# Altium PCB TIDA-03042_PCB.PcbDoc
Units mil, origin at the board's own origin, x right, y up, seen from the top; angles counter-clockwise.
Board outline 1000 x 1000 mil, 4 copper layers (Top Layer, GND, POWER_SPLIT_PLANE, Bottom Layer), stack 0 mil thick; 34 components, 18 nets, 98 pads, 123 vias.
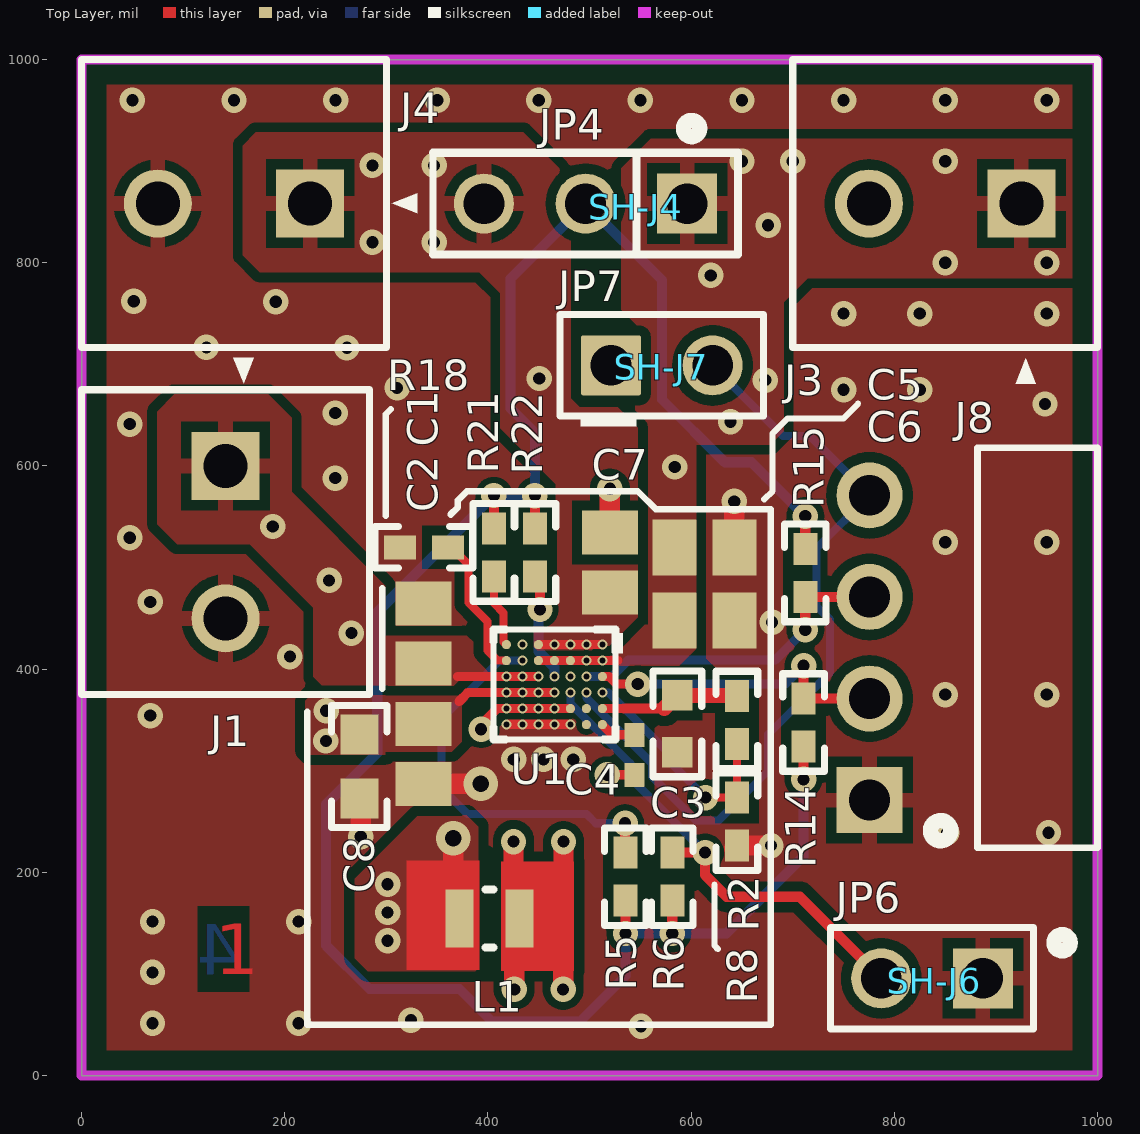
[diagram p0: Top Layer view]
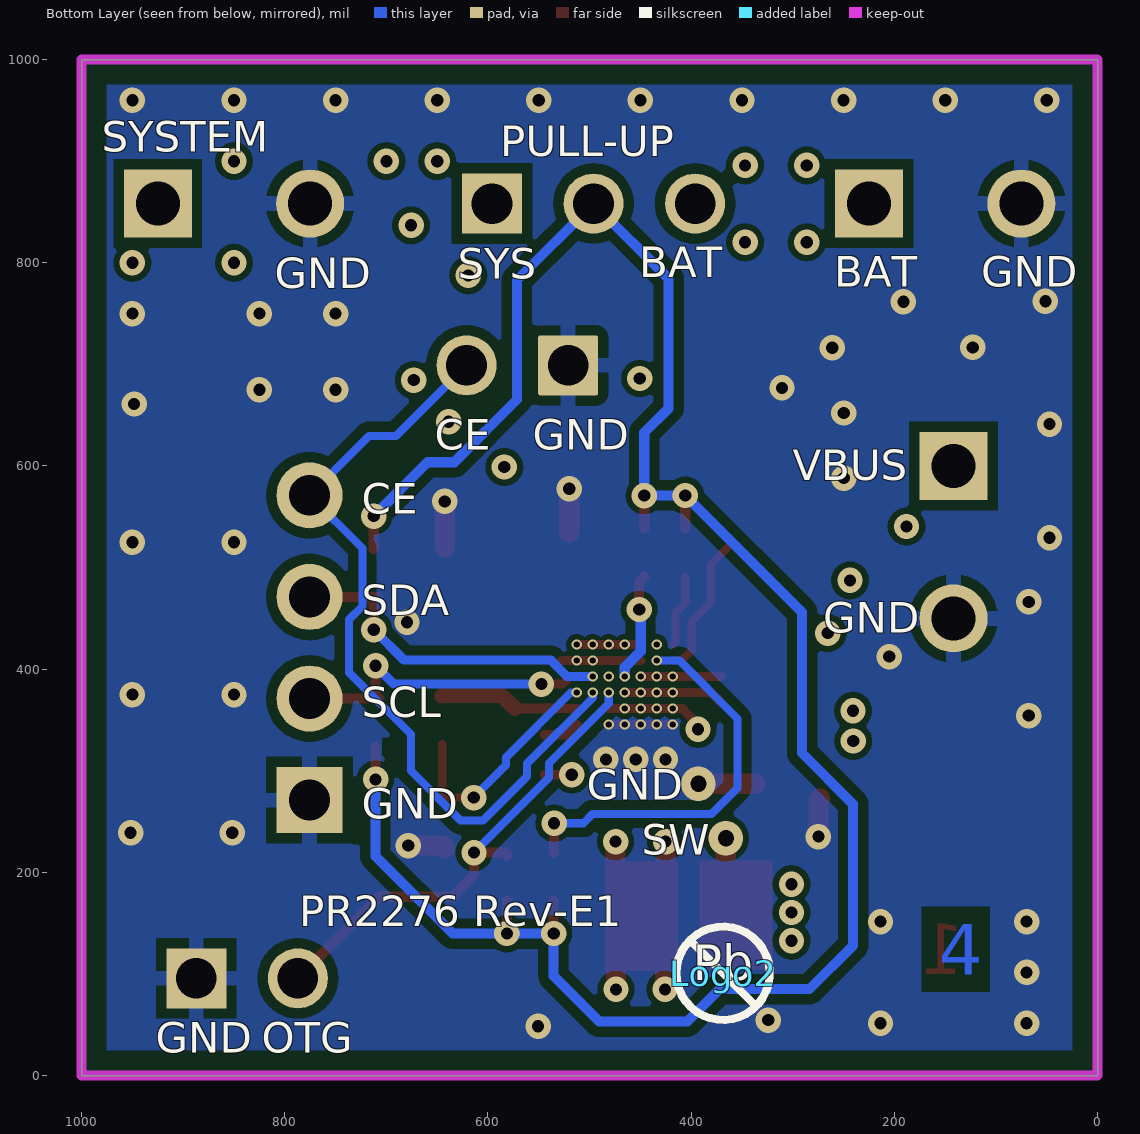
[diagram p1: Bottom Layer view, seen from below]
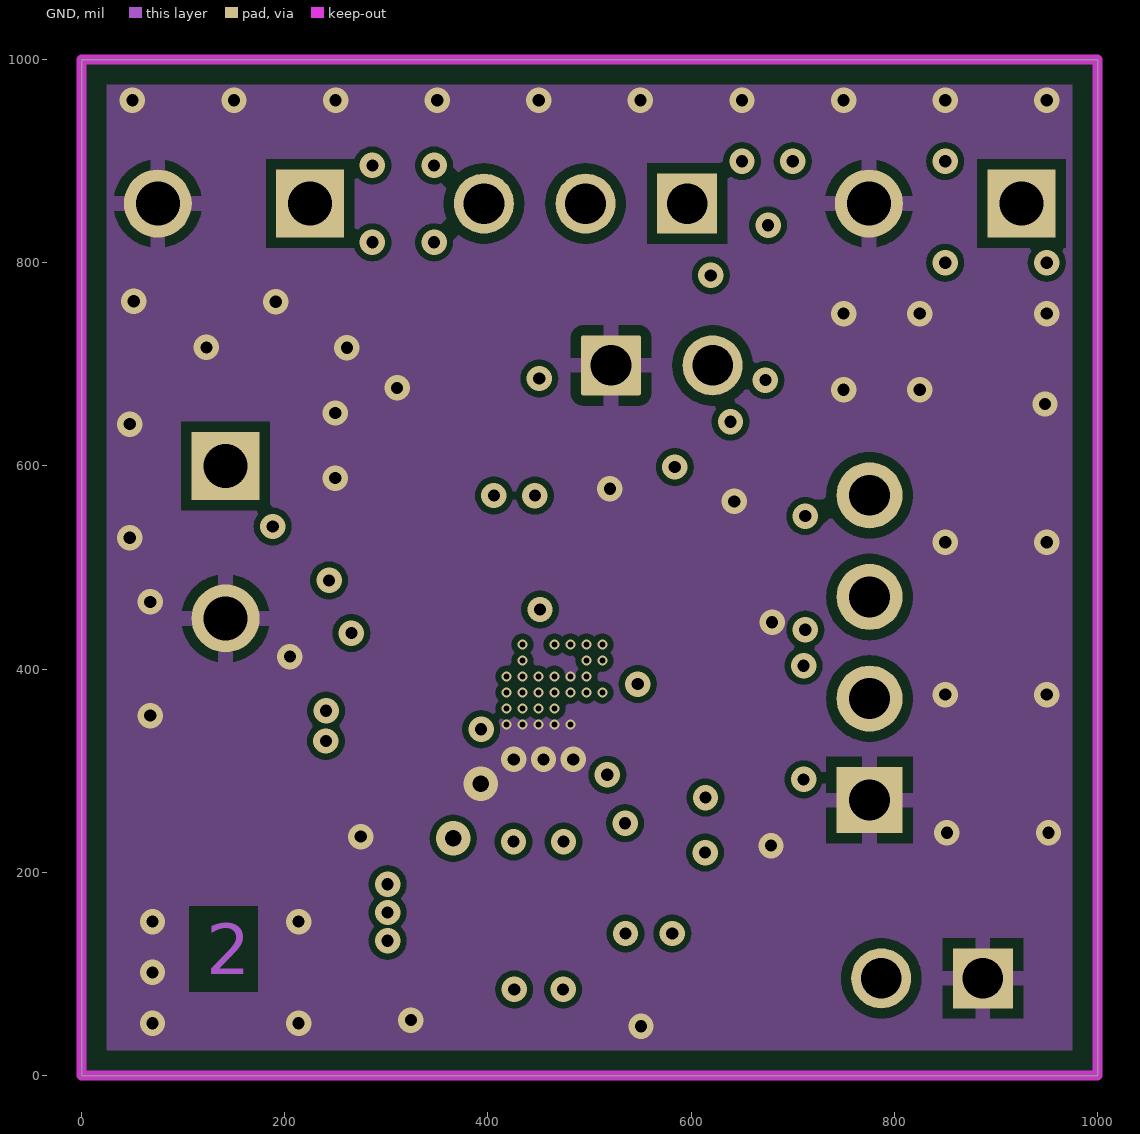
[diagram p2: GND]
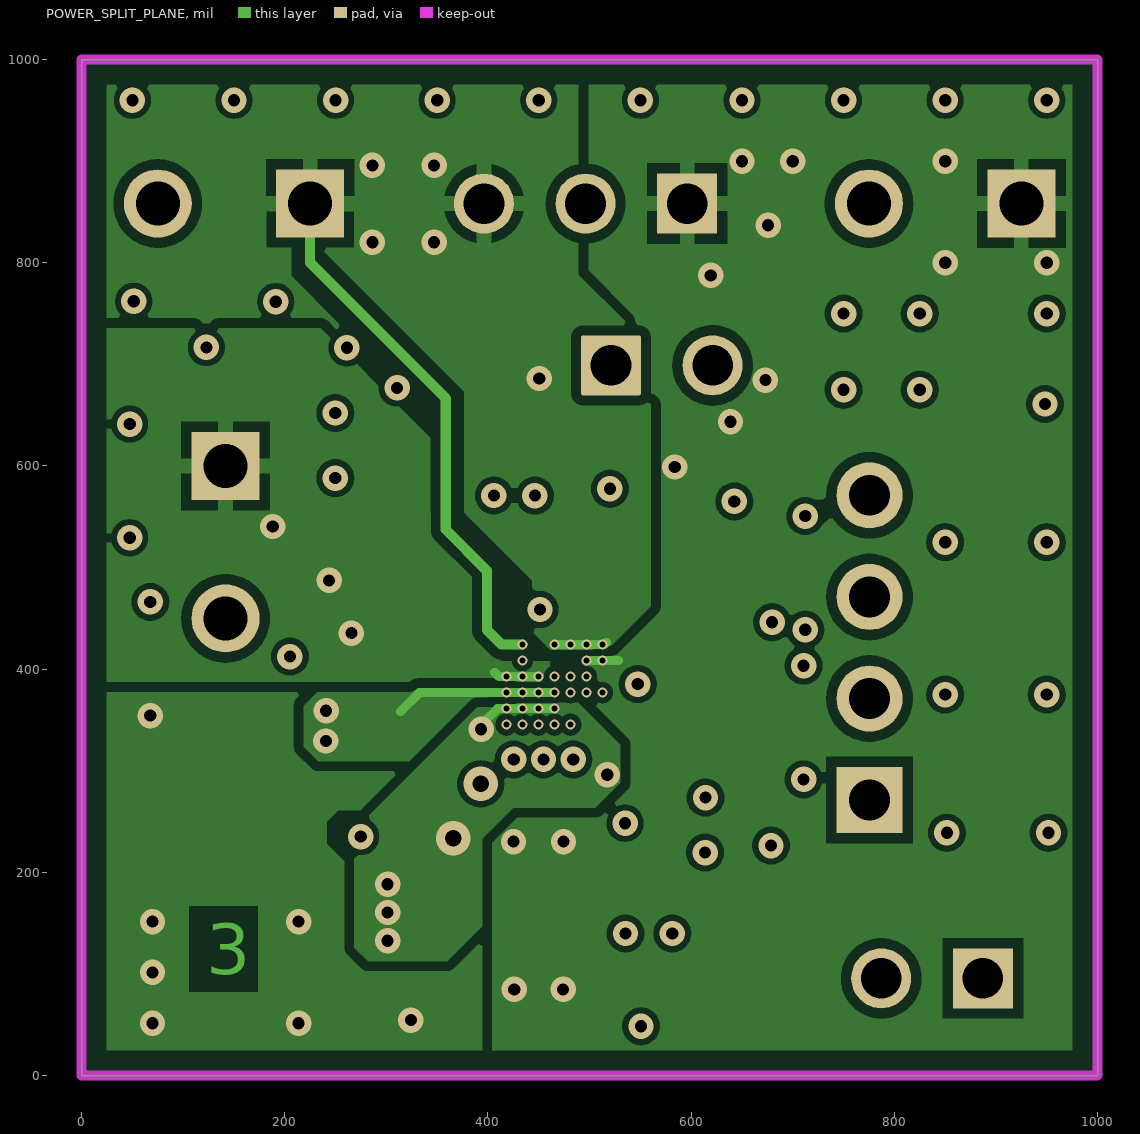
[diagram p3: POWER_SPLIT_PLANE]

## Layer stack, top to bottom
Top Layer: signal copper (thickness not stored)
GND: signal copper (thickness not stored)
POWER_SPLIT_PLANE: signal copper (thickness not stored)
Bottom Layer: signal copper (thickness not stored)

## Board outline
0,0 1000,0 1000,1000 0,1000

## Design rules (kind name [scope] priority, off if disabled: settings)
AcuteAngle [All] p1: minimum=4.50000000000000E+0001 checktracksonly=FALSE
AssemblyTestPointUsage [All] p1: valid=2
Clearance Clearance_RoomU1 [WithinRoom('Room_U1')] p1: gap=5.74
Clearance Clearance_Keepouts [((IsTrack Or IsArc) And Not InPoly) And IsFree and IsKeepOut vs ((IsTrack Or IsArc) And Not InPoly) And IsFree and IsKeepOut] p2: gap=0
Clearance Clearance_BoardEdge_MountingHoles [OnCopper and InComponentClass('Mounting Holes') vs IsKeepOut] p3: gap=40
Clearance Clearance_BoardEdge_Poly [OnCopper and InPoly vs IsKeepOut] p4: gap=20
Clearance Clearance_BoardEdge [OnCopper and Not InComponentClass('Logo') and not InComponentClass('FiducialMark') and not InRegion(1000,500,4000,800) and Not IsKeepout vs IsKeepOut] p5: gap=22
Clearance Clearance_Poly [InPolygon] p6: gap=10 except(6: Via-Poly)
Clearance Clearance_U1-area [InRegionRelative(1450,2050,1615,2170)] p7: gap=5.7
Clearance [All] p8: gap=6
ComponentClearance ComponentClearance_TOP&BOTTOM [InComponentClass('Top Side Components') vs InComponentClass('Bottom Side Components')] p1: gap=0 collisioncheckmode=3 verticalgap=0 showdistances=FALSE
ComponentClearance ComponentClearance_Shunt [hasfootprint('CONN_PEC02SAAN') or   hasfootprint('CONN_PEC03SAAN') vs InComponentClass('Shunt')] p2: gap=0 collisioncheckmode=3 verticalgap=0 showdistances=FALSE
ComponentClearance ComponentClearance_THtoTH [IsThruComponent vs IsThruComponent] p3: gap=10 collisioncheckmode=3 verticalgap=10 showdistances=FALSE
ComponentClearance [All] p4: gap=7 collisioncheckmode=3 verticalgap=10 showdistances=FALSE
DiffPairsRouting [All] p1: maxlimit=100 minlimit=10 mostfreqgap=10 toplayer_minwidth=15 toplayer_maxwidth=15 toplayer_prefwidth=15 midlayer1_minwidth=15 midlayer1_maxwidth=15 midlayer1_prefwidth=15 midlayer2_minwidth=15 midlayer2_maxwidth=15 midlayer2_prefwidth=15 bottomlayer_minwidth=15 bottomlayer_maxwidth=15 bottomlayer_prefwidth=15 maxuncoupledlength=1000
FabricationTestPointUsage TestPointUsage [All] p1: valid=2 allowmultiple=FALSE
FabricationTestpoint Testpoint [All] p1: side=3 testpointundercomponent=TRUE minsize=40 maxsize=100 preferedsize=60 minholesize=0 maxholesize=40 preferedholesize=32 testpointgrid=1 allowsidetop=TRUE allowsidebottom=TRUE usegrid=TRUE gridtolerance=0.01
FanoutControl Fanout_LCC [IsLCC] p1: bgadir=Out bgaviamode=Centered fanoutstyle=Auto fanoutdirection=Alternating viagrid=1 // Fanout_LCC (Default Rule)
FanoutControl Fanout_BGA [IsBGA] p2: bgadir=Out bgaviamode=Centered fanoutstyle=Auto fanoutdirection=Alternating viagrid=1 // Fanout_BGA (Default Rule)
FanoutControl Fanout_Default [All] p4: bgadir=Out bgaviamode=Centered fanoutstyle=Auto fanoutdirection=Alternating viagrid=1 // Fanout_Default (Default Rule)
FanoutControl Fanout_Small [(CompPinCount < 5)] p5: bgadir=Out bgaviamode=Centered fanoutstyle=Auto fanoutdirection=OutThenIn viagrid=1 // Fanout_Small (Default Rule)
HoleSize [All] p1: absolutevalues=TRUE maxlimit=251 minlimit=6 maxpercent=80.000 minpercent=20.000
HoleToHoleClearance [All] p1: gap=9.7 allowstackedmicrovias=TRUE
MinimumAnnularRing MinimumAnnularRing_ThermalPadVias [IsVia] p1: minimumring=2
MinimumAnnularRing [All] p2: minimumring=7.5
MinimumSolderMaskSliver [All] p1: minsoldermaskwidth=3
PlaneConnect [All] p1: planeconnectstyle=Relief reliefexpansion=10 reliefentries=4 reliefconductorwidth=10 reliefairgap=10
PolygonConnect PolygonConnect_PTH [InPadClass('PTH')] p1: connectstyle=Relief reliefconductorwidth=15 reliefentries=4 polygonreliefangle="90 Angle" airgapwidth=10
PolygonConnect [All] p2: connectstyle=Direct reliefconductorwidth=10 reliefentries=4 polygonreliefangle="90 Angle" airgapwidth=10
RoomDefinition Room_U1 [All] p1: confinementstyle=ConfineOut formatcopy=TRUE lockcomponents=FALSE outline 406.14,438.95 525.42,438.95 525.42,331.46 406.14,331.46
RoutingVias ThermalPadVias [IsVia and InAnyComponent] p1: holewidth=7.87 width=19.68 viastyle="Through Hole" minholewidth=7.87 minwidth=19.68 maxholewidth=12.99 maxwidth=23.62
RoutingVias [All] p2: holewidth=10 width=22 viastyle="Through Hole" minholewidth=6 minwidth=10 maxholewidth=40 maxwidth=65
SilkToBoardRegionClearance [All] p1 off:
SilkToSilkClearance SilkToSilkClearance_PB [HasFootprint('Pb-Free_Overlay_Small')] p1: silktosilkclearance=0
SilkToSilkClearance [All] p2: silktosilkclearance=3
SilkToSolderMaskClearance "Silk to Solder Mask Opening" [IsPad] p1: minsilkscreentomaskgap=4 clearancetoexposedcopper=TRUE
SolderMaskExpansion SolderMaskExpansion_PTH [InPadClass('PTH')] p1: expansion=2.5
SolderMaskExpansion [All] p2: expansion=0
Width [All] p1: maxlimit=100 minlimit=7.8 preferedwidth=10 checkconnectedcopper=TRUE
14 further rules are at their usual default settings.

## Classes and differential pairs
component class PR2276E1_Hardware: Logo2 ZZ1 ZZ2 ZZ3 ZZ4
component class AssemblyNote: ZZ1 ZZ2 ZZ3 ZZ4
component class PR2276E1: C1 C2 C3 C4 C5 C6 C7 C8 J1 J3 J4 J8 JP4 JP6 JP7 L1 R2 R5 R6 R8 R14 R15 R18 R21 R22 SH-J4 SH-J6 SH-J7 U1
pad class PTH: J1-1 J1-2 J3-1 J3-2 J4-1 J4-2 J8-1 J8-2 J8-3 J8-4 JP4-1 JP4-2 JP4-3 JP6-1 JP6-2 JP7-1 JP7-2
component class Shunt: SH-J4 SH-J6 SH-J7

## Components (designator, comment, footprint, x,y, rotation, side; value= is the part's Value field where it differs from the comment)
C1 "GRM219R71E105KA88D" 0805L 336.71,434.96 r90 top
C2 "C2012X5R1E106K125AB" 0805L 336.71,316.66 r270 top
C3 "GRM188R61C475KAAJ" 0603_HV 586.44,346.18 r270 top
C4 "GRM155R71E473KA88D" 0402L 544.2,315.73 r90 top
C5 "C2012X5R1C226M125AC" 0805L 612.96,519.98 r0 top
C6 "GRM21BR71A106KE51L" 0805L 612.96,447.93 r0 top
C7 "GRM21BR71A106KE51L" 0805L 520,505 r270 top
C8 "GRM188R71E102KA01D" 0603 273.45,304.18 r90 top
J1 "1727010" PhoenixConact_1727010 141.73,525 r270 top locked
J3 "1727010" PhoenixConact_1727010 850,858.27 r180 top locked
J4 "1727010" PhoenixConact_1727010 150,858.3 r180 top locked
J8 "22-05-3041" CONN_22-05-3041 1000,421.12 r90 top locked
JP4 "PEC03SAAN" CONN_PEC03SAAN 496.06,858.27 r180 top locked
JP6 "PEC02SAAN" CONN_PEC02SAAN#1 837.09,95.72 r180 top
JP7 "PEC02SAAN" CONN_PEC02SAAN#2 571.08,699.03 r0 top
L1 "74479275210" WE-PMCI_0805 401.55,154.72 r0 top
Logo2 "Pb-Free Symbol" Pb-Free_Overlay_Small 368.64,100.73 r180 bottom
R2 "CRCW040210K0FKED" 0402 645,350 r90 top
R5 "CRCW040210K0FKED" 0402 535.33,195.76 r270 top
R6 "CRCW040210K0FKED" 0402 581.41,195.76 r270 top
R8 "CRCW040210K0FKED" 0402 645,250 r90 top
R14 "CRCW040210K0FKED" 0402 710.63,347.5 r90 top
R15 "CRCW040210K0FKED" 0402 712.37,494.74 r270 top
R18 "CRCW0402232RFKED" 0402 337,520 r0 top
R21 "CRCW04022K21FKED" 0402 405.83,514.9 r90 top
R22 "CRCW04022K21FKED" 0402 446.18,514.8 r90 top
SH-J4 "SNT-100-BK-G" SNT-100-BK-G 545.28,855.37 r180 top
SH-J6 "SNT-100-BK-G" SNT-100-BK-G 839.19,93.46 r180 top
SH-J7 "SNT-100-BK-G" SNT-100-BK-G 570.74,697.87 r180 top
U1 "BQ25898YFFR" YFF0042-C01 465.38,384.81 r270 top
ZZ1 "This Assembly Note is for PCB labels only" AssemblyNoteLabel 9.76,1694.48 r0 top
ZZ2 "These assemblies are ESD sensitive, ESD precautions shall be observed." AssemblyNote 9.76,1585.59 r0 top
ZZ3 "These assemblies must be clean and free from flux and all contaminants. Use of no clean flux is not acceptable." AssemblyNote 9.76,1497.04 r0 top
ZZ4 "These assemblies must comply with workmanship standards IPC-A-610 Class 2, unless otherwise specified." AssemblyNote 9.76,1408.48 r0 top

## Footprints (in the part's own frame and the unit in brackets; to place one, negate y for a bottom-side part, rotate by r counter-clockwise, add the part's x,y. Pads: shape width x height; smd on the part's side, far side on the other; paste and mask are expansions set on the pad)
0402 [mm] "0402 from SM-752 data"
  rect 0.8x0.6 smd: 1(-0.6,0) 2(0.6,0)
  silkscreen extent -1.22,-0.52 1.22,0.52, body extent -0.55,-0.3 0.55,0.3, height 0.6
0402L [mm] "0402 from SM-752 data"
  rect 0.6x0.5 smd: 1(-0.5,0) 2(0.5,0)
  body extent -0.55,-0.3 0.55,0.3, height 0.6
0603 [mm] "0603 from SM-752 data"
  rect 1x0.95 smd: 1(-0.8,0) 2(0.8,0)
  silkscreen extent -1.52,-0.69 1.52,0.69, body extent -0.87,-0.47 0.87,0.47, height 1
0603_HV [mil] "Ernesto recommended land pattern.  26 mil between pads."
  rect 30x30 smd: 1(-28,0) 2(28,0)
  silkscreen extent -52,-24 52,24, body extent -34,-19 34,19, height 33
0805L [mm] "0805 from SM-752 data"
  rect 1.1x1.4 smd: 1(-0.75,0) 2(0.75,0)
  body extent -1.1,-0.72 1.1,0.72, height 1.1
AssemblyNote [mil] "Assembly Note"
AssemblyNoteLabel [mil] "Assembly Note for PCB Labels"
CONN_22-05-3041 [mm] "MOLEX"
  rect 1.65x1.65 hole 1.02: 1(-3.81,5.7)
  round 1.65 hole 1.02: 2(-1.27,5.7) 3(1.27,5.7) 4(3.81,5.7)
  silkscreen extent -5,0 5,4.18, body extent -5,-6.91 5,6.02, height 6.37
CONN_PEC02SAAN#1 [mm] "SULLINS"
  rect 1.5x1.5 hole 1.016: 1(-1.27,0)
  round 1.5 hole 1.016: 2(1.27,0)
  silkscreen extent -3.45,-1.27 2.54,1.27, body extent -2.54,-1.27 2.54,1.27, height 8.38
CONN_PEC02SAAN#2 [mm] "SULLINS"
  rrect7% 1.5x1.5 hole 1.016: 1(-1.27,0)
  round 1.5 hole 1.016: 2(1.27,0)
  silkscreen extent -2.54,-1.52 2.54,1.27, body extent -2.54,-1.27 2.54,1.27, height 8.38
CONN_PEC03SAAN [mm] "SULLINS"
  rect 1.5x1.5 hole 1.016: 1(-2.54,0)
  round 1.5 hole 1.016: 2(0,0) 3(2.54,0)
  silkscreen extent -3.81,-2.08 3.81,1.27, body extent -3.84,-1.3 3.84,1.3, height 8.38
Pb-Free_Overlay_Small [mil]
  silkscreen extent -46,-46 46,46
PhoenixConact_1727010 [mm]
  rect 1.7x1.7 hole 1.1: 1(-1.905,0)
  round 1.7 hole 1.1: 2(1.905,0)
  silkscreen extent -4.61,-3.6 3.81,3.6, body extent -3.81,-3.6 3.81,3.7, height 8.52
SNT-100-BK-G [mil] "Samtec STEP model"
  round 1 on Mech3: 0(0,0)
  body extent -100,-50 100,50, height 344
WE-PMCI_0805 [mm] "SMD, 2-Leads, Body 2x1.25mm"
  rect 0.7x1.45 smd: 1(-0.75,0) 2(0.75,0)
  silkscreen extent -0.1,-0.72 0.1,0.72, body extent -1,-0.62 1,0.63, height 1
YFF0042-C01 [mm] "BGA, 42-Balls, Body 2.82x2.53mm, Pitch 0.4mm"
  round 0.23 smd paste-0.2 mask+0.038: A1(-1,1.2) A2(-0.6,1.2) A3(-0.2,1.2) A4(0.2,1.2) A5(0.6,1.2) A6(1,1.2) B1(-1,0.8) B2(-0.6,0.8) B3(-0.2,0.8) B4(0.2,0.8) B5(0.6,0.8) B6(1,0.8) C1(-1,0.4) C2(-0.6,0.4) C3(-0.2,0.4) C4(0.2,0.4) C5(0.6,0.4) C6(1,0.4) D1(-1,0) D2(-0.6,0) D3(-0.2,0) D4(0.2,0) D5(0.6,0) D6(1,0) E1(-1,-0.4) E2(-0.6,-0.4) E3(-0.2,-0.4) E4(0.2,-0.4) E5(0.6,-0.4) E6(1,-0.4) F1(-1,-0.8) F2(-0.6,-0.8) F3(-0.2,-0.8) F4(0.2,-0.8) F5(0.6,-0.8) F6(1,-0.8) G1(-1,-1.2) G2(-0.6,-1.2) G3(-0.2,-1.2) G4(0.2,-1.2) G5(0.6,-1.2) G6(1,-1.2)
  silkscreen extent -1.37,-1.53 1.38,1.53, body extent -1.28,-1.42 1.28,1.42, height 0.63

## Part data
C1: "CAP, CERM, 1 µF, 25 V, +/- 10%, X7R, 0805"
C2: "CAP, CERM, 10uF, 25V, +/-10%, X5R, 0805"
C3: "CAP, CERM, 4.7uF, 16V, +/-10%, X5R, 0603"
C4: "CAP, CERM, 0.047uF, 25V, +/-10%, X7R, 0402"
C5: "CAP, CERM, 22 µF, 16 V, +/- 20%, X5R, 0805"
C6 C7: "CAP, CERM, 10 µF, 10 V, +/- 10%, X7R, 0805"
C8: "CAP, CERM, 1000 pF, 25 V, +/- 10%, X7R, 0603"
J1 J3 J4: "Conn Term Block, 2POS, 3.81mm, TH"
J8: "Header, 100mil, 4x1, R/A, TH"
JP4: "Header, 100mil, 3x1, Tin plated, TH"
JP6 JP7: "Header, 100mil, 2x1, Tin plated, TH"
L1: "Inductor, Shielded, 1 µH, 1.8 A, 0.078 ohm, SMD"
Logo2: library part Pb-Free
R2 R5 R6 R8 R14 R15: "RES, 10.0k ohm, 1%, 0.063W, 0402"
R18: "RES, 232, 1%, 0.063 W, 0402"
R21 R22: "RES, 2.21k ohm, 1%, 0.063W, 0402"
SH-J4 SH-J6 SH-J7: "Shunt, 100mil, Gold plated, Black"
U1: "I2C Controlled 4A Single Cell NVDC Power Path Management with MaxChargeTM High Voltage Adapter Support, YFF0042-C01"
ZZ1: library part AssemblyNoteLabel
ZZ2 ZZ3 ZZ4: library part AssemblyNote

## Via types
v1: diameter 25, hole 12, Top Layer to Bottom Layer, tented both sides, 91 vias
v2: diameter 10, hole 6, Top Layer to Bottom Layer, tented bottom, 30 vias
v3: diameter 34, hole 16, Top Layer to Bottom Layer, 2 vias

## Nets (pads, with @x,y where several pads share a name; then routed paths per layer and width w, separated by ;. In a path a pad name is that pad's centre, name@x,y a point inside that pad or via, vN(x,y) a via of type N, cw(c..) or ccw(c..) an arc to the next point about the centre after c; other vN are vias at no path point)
\CE: J8.4 JP7.2 U1.B4 | length 792.7
  Bottom Layer w8: v2(496.88,376.93) 496.88,371.83 561.47,307.24 561.47,294.4 604.75,251.12 627.01,251.12 675.89,300 675.89,336 736.66,396.77 736.66,448.75 723.48,461.93 723.48,519.01 J8.4 717.16,629.55 690.57,629.55 JP7.2
GND: C1.2 C2.2 C3.2 C5.2 C6.2 C7.1 C8.1 J1.2 J3.2 J4.2 J8.1 JP6.1 JP7.1 R8.1 R18.1 U1.C3 U1.C6 U1.D6 U1.E6 U1.F6 U1.G6 | length 282.5
  Top Layer w9.05: v2(418.14,345.44) v2(433.89,345.44) v2(449.63,345.44) v2(465.38,345.44) v2(481.13,345.44)
  Top Layer w20: C8.1 274.74,271.39 v1(274.74,235.17) ; C2.2 v3(392.86,287.13) ; C7.1 v1(520,577.59) ; R8.1@642.47,223.85 R8.1 v1(678.54,226.38) ; C5.2 v1(642.49,565.13)
  other v1: 550.65,48.51 69.8,51.55 213.67,51.55 324.17,54.59 69.8,101.55 69.8,151.55 213.67,151.55 851.71,238.97 951.71,238.97 425.29,311.23 454.62,311.23 483.94,311.23 67.7,354.32 850,375 950,375 205.08,412.41 679.64,446.19 67.7,466.19 850,525 950,525 47.34,529.35 249.75,588.05 47.34,641.22 249.75,652.18 948.29,661.03 750,675 825,675 310.56,676.88 261.19,716.31 122.83,716.68 750,750 825,750 950,750 51.37,762.06 191.1,761.63 50,960 150,960 250,960 350,960 450,960 550,960 650,960 750,960 850,960 950,960
  other v2: 481.13,392.68
ILIM: R18.2 U1.G2 | length 139.3
  Top Layer w8: R18.2@363.62,520 380.68,502.94 380.68,465.75 399.38,447.05 399.38,418.44 409.4,408.43 U1.G2
NetC4_1: C4.1 L1.1 U1.C5 U1.D5 U1.E5 U1.F5 U1.G5 | length 280
  Top Layer w9.05: v1(393.29,340.89) 393.29,345.61 408.87,361.18 v2(418.14,361.18) v2(433.89,361.18) v2(449.63,361.18) v2(465.38,361.18) U1.C5 ; v1(517.49,296.04) C4.1
  Top Layer w20: v3(365.83,233.52) 365.83,160.92 L1.1
  POWER_SPLIT_PLANE w9.05: v1@397.46,349.14 409.5,361.18 v2(418.14,361.18) v2(433.89,361.18) v2(449.63,361.18) v2(465.38,361.18)
  other v1: 301.26,132.69 301.26,160.53 301.26,188.37
NetC4_2: C4.2 U1.A6 | length 35.7
  Top Layer w9.05: U1.A6 522.65,335.41 C4.2
NetC5_1: C5.1 C6.1 J3.1 JP4.1 L1.2 U1.A2 U1.B2 U1.C2 U1.D2 U1.E2 | length 431.1
  Top Layer w9.05: U1.E2 U1.D2 U1.C2 v2(496.88,408.43) v2(512.63,408.43) 527.64,408.43
  Top Layer w20: v1@425.15,231.55 v1(425.15,230.3) 425.15,197.63 L1.2@442.11,180.68 ; v1(425.8,84.82) L1.2@425.8,126.53 ; L1.2 460.21,125.59 ; L1.2@442.11,167.36 L1.2@442.11,180.68 ; L1.2@442.51,164.96 L1.2@444.51,164.96 ; L1.2@442.51,167.36 444.91,164.96 474.39,164.96 ; 444.56,196.46 444.9,196.46 ; 460.21,188.58 460.21,196.46 ; v1(473.95,84.79) 473.95,126.52 ; v1(474.39,230.3) 474.39,196.46 460.21,196.46 ; L1.2@442.11,180.68 442.11,193.67 444.9,196.46 ; 444.9,196.46 446.56,196.46 ; 444.9,196.46 445.73,197.29 446.56,196.46 ; 446.56,196.46 460.21,196.46
  POWER_SPLIT_PLANE w9.05: v2(496.88,408.43) v2(512.63,408.43) 528.36,408.43
  other v1: 583.91,598.97 638.74,643.61 673.02,684.51 619.36,787.64 850,800 950,800 675.69,836.86 650,900 700,900 850,900
NetC7_2: C7.2 J4.1 JP4.3 U1.A1 U1.B1 U1.C1 U1.D1 U1.E1 U1.F1 | length 647.4
  Top Layer w9.05: U1.E1 v2(465.38,424.18) v2(481.13,424.18) v2(496.88,424.18) v2(512.63,424.18)
  POWER_SPLIT_PLANE w9.05: v2(465.38,424.18) v2(481.13,424.18) v2(496.88,424.18) v2(512.63,424.18) 514.27,424.18 v2@516.36,426.26
  POWER_SPLIT_PLANE w10: J4.1 225,799.97 358.46,666.51 358.46,537.47 398.93,497 398.93,438.84 413.59,424.18 v2(433.89,424.18)
  other v1: 450.56,686.08 286.22,820.12 346.95,820.12 286.22,895.85 346.95,895.85
NetJP6_2: JP6.2 R6.1 U1.C4 | length 486.7
  Top Layer w10: R6.1 581.41,216.3 584.62,219.51 v1(613.72,219.51) 613.72,197.31 635.06,175.96 706.85,175.96 JP6.2
  Bottom Layer w8: v2(481.13,376.93) 481.13,366.28 539.99,307.42 539.99,293.24 v1(613.72,219.51)
NetR2_1: R2.1 R8.2 U1.A4 | length 232.4
  Top Layer w8: v1(614.07,273.62) R8.2 R2.1
  Bottom Layer w8: v2(512.63,376.93) 518.47,376.93 582.14,313.26 582.14,305.55 v1(614.07,273.62)
NetR5_1: R5.1 U1.F2 | length 395.4
  Top Layer w10: v1(534.95,248.41) 534.95,219.76 R5.1
  Bottom Layer w8: v2(433.89,408.43) 411.63,408.43 354.39,351.19 354.39,283.14 379.95,257.58 496.96,257.58 506.13,248.41 v1(534.95,248.41)
PG: R22.1 U1.D3 | length 107.7
  Top Layer w10: R22.1 451.18,486.18 v1(451.18,458.8)
  Bottom Layer w10: v1(451.18,458.8) 449.64,457.25 449.64,417.66 465.38,401.92 v2(465.38,392.68)
PMID: C2.1 C8.2 U1.D4 U1.E4 U1.F4 U1.G4 | length 256.4
  Top Layer w9.05: 371.46,368.2 380.18,376.93 v2(418.14,376.93) v2(433.89,376.93) v2(449.63,376.93) v2(465.38,376.93)
  POWER_SPLIT_PLANE w9.05: 314.18,358.47 332.63,376.93 v2(418.14,376.93) v2(433.89,376.93) v2(449.63,376.93) v2(465.38,376.93)
  other v1: 240.5,329.3 240.71,359.13
PULL-UP: JP4.2 R5.2 R6.2 R14.1 R15.1 R21.2 R22.2 | length 2154.8
  Top Layer w10: R21.2 v1(405.83,570.91) ; R22.2 v1(446.18,570.81) ; v1(535.33,139.82) R5.2 ; v1(581.41,139.82) R6.2 ; v1(710.63,291.56) R14.1 ; R15.1 v1(712.37,550.67)
  Bottom Layer w10: v1(710.63,291.56) 710.63,215.79 634.67,139.82 v1(581.41,139.82) v1(535.33,139.82) 535.33,97.97 490.59,53.23 403.92,53.23 371.94,85.21 283.47,85.21 240.73,127.95 240.73,267.21 290.97,317.44 290.97,456.04 v1(405.83,570.91) 446.09,570.91 v1(446.18,570.81) 446.18,632.89 422.21,656.86 422.21,784.42 JP4.2 571.35,782.98 571.35,665.44 633.17,603.61 659.43,603.61 v1(712.37,550.67)
REGN: C3.1 R2.2 U1.A5 | length 138
  Top Layer w9.05: U1.A5 533.8,361.18
  Top Layer w10: 533.8,361.18 C3.1@573.44,361.18
  Top Layer w15: C3.1@573.44,361.18 C3.1 644.44,374.18 R2.2
SCL: J8.2 R14.2 U1.A3 | length 309.8
  Top Layer w9.05: U1.A3 519.34,392.68 526.71,385.31 v1(547.42,385.31)
  Top Layer w10: R14.2@706.63,371.12 R14.2 ; v1(710.63,403.43) R14.2 ; J8.2 R14.2
  Bottom Layer w9.05: v1(547.42,385.31) 692.51,385.31 v1(710.63,403.43)
SDA: J8.3 R15.2 U1.B3 | length 334.1
  Top Layer w10: R15.2@708.37,471.12 R15.2 ; v1(712.37,438.81) R15.2 ; J8.3 R15.2
  Bottom Layer w9.05: v2(496.88,392.68) 521.86,392.68 538.22,409.04 682.6,409.04 v1(712.37,438.81)
STAT: R21.1 U1.G1 | length 72.2
  Top Layer w8: R21.1 405.83,464.85 415.38,455.3 415.38,426.93 U1.G1
VBUS: C1.1 J1.1 U1.E3 U1.F3 U1.G3 | length 123.9
  Top Layer w9.05: 370.36,392.68 v2(418.14,392.68) v2(433.89,392.68) v2(449.63,392.68)
  POWER_SPLIT_PLANE w9.05: 406.66,396.78 410.77,392.68 v2(418.14,392.68) v2(433.89,392.68) v2(449.63,392.68)
  other v1: 265.54,435.56 243.65,487.41 188.09,540.49
pads on no net: SH-J4.0 SH-J6.0 SH-J7.0 U1.B5 U1.B6

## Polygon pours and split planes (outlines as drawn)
GND on GND "GND-GND" (solid, remove dead copper, pour order 118): 0,1000 0,0 1000,0 1000,1000
PMID on Top Layer "TOP_PMID" (solid, remove dead copper, pour order 113): 471.92,374.13 225.35,374.13 220,368.78 220,319.89 224.19,315.7 361.42,315.7 374.14,328.42 374.14,364.12 381.34,371.32 471.92,371.32
VBUS on Top Layer "TOP_VBUS" (solid, remove dead copper, pour order 114): 379.35,432.83 348.54,432.83 206.63,574.74 206.63,647.53 183.58,670.59 91.36,670.59 74.38,653.61 74.38,542.77 94.03,523.12 165.52,523.12 228.19,460.45 228.19,392.37 237.21,383.35 391.73,383.35 399.45,391.07 399.45,412.74
NetC7_2 on Top Layer "TOP_NETC7_2" (solid, remove dead copper, pour order 115): 445.09,447.38 445.09,422.13 448.67,418.56 514.91,418.4 517.86,421.35 547.65,451.14 547.65,637.84 527.77,657.72 490.29,657.72 481.48,666.52 481.48,881.71 434.79,928.41 171.64,928.41 158.66,915.42 158.66,807.45 175.59,790.52 391.64,790.52 412.05,770.1 412.05,636.92 466.83,582.14 466.83,469.12
NetC5_1 on Top Layer "TOP_NETC5_2" (solid, remove dead copper, pour order 116): 545,739.91 531.36,753.56 531.35,893.12 560.32,922.09 978.46,922.09 978.46,784.81 714.97,784.81 691.11,760.94 691.11,634.02 678.03,620.94 605,620.94 605,420 588.45,403.45 509.97,403.45 506.83,406.6 506.83,410.92 509.82,413.91 520.44,413.91 545,438.48
GND on Top Layer "GND-GND" (solid, remove dead copper, pour order 117): 0,1000 0,0 1000,0 1000,1000
NetC4_1 on Top Layer "POWER_NetC4_1" (solid, remove dead copper, pour order 112): 268.67,193.71 268.67,115.42 281.55,102.55 390.5,102.55 390.5,245 378.84,256.66 331.63,256.66
NetC7_2 on POWER_SPLIT_PLANE "POWER_NETC7_2" (solid, remove dead copper, pour order 122): 517.37,419.12 461.29,419.12 443.7,436.71 443.7,487.16 190.19,740.68 15,740.68 -0.09,755.77 -0.09,999.94 488.97,1000.02 488.97,788.37 560.35,717 560.35,462.1
NetC4_1 on POWER_SPLIT_PLANE "POWER_NetC4_1" (solid, remove dead copper, pour order 119): 268.58,241.35 268.58,126.04 281.98,112.64 359.77,112.64 394.23,147.1 394.23,233.17 424.79,263.73 505.84,263.73 530.4,288.29 530.4,325.52 488.91,367 394.23,367
NetC5_1 on POWER_SPLIT_PLANE "POWER-NetC5_1" (solid, remove dead copper, pour order 123): 404.22,1000 404.22,0 1000,0 1000,1000
PMID on POWER_SPLIT_PLANE "POWER_PMID" (solid, remove dead copper, pour order 121): 383.55,309.44 233.05,309.43 218.58,323.9 218.58,364.25 236.28,381.95 487.91,381.95 500.22,369.63 500.22,329.27 403.39,329.27
VBUS on POWER_SPLIT_PLANE "POWER_VBUS" (solid, remove dead copper, pour order 120): 460.73,387.51 3.38,387.5 3.38,735.7 235.51,735.7 411.87,559.34 411.87,407.99 460.73,407.99
GND on POWER_SPLIT_PLANE "GND-GND" (solid, remove dead copper, pour order 126): 0,1000 0,0 1000,0 1000,1000
GND on Bottom Layer "GND-GND" (solid, remove dead copper, pour order 124): 0,1000 0,0 1000,0 1000,1000

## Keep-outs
Keep-Out Layer:
  the board outline again, w10
  text ".Layer_Name" at 577,-858.49 h60

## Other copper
Top Layer:
  rectangle net NetC5_1: 412.84,103.02 484.84,210.52
  rectangle net NetC4_1: 319.84,104.02 391.84,211.52
  pour cut-out: 615.09,410.37 626.01,399.45 626.01,393.56 618.47,386.02 611.04,386.02 602.14,394.92 602.14,402.87 609.64,410.37
  pour cut-out: 391.29,92.93 391.29,220.6 414.55,220.6 414.55,92.93
  pour cut-out: 492.58,822.57 488.66,818.66 488.66,737.02 490.06,735.62 525.85,735.62 531.04,740.82 531.04,825.48 525.29,831.24
  pour cut-out: 505.58,586.56 510.65,591.63 526.45,591.63 536.18,581.91 536.18,560.74 544.48,552.43 544.48,519.61 539.72,514.85 500.72,514.85 495.86,519.71 495.86,549.8 495.86,557.49 505.59,567.22
  pour cut-out: 544.92,739.99 546.62,738.3 546.62,737.2 544.92,738.64
  text "1" at 131.26,99.6 h50
  text ".Layer_Name" at 577,-858.49 h60
GND:
  pour cut-out: 354.07,837.86 359.55,843.35 361.01,843.35 370.85,833.5 370.85,827.8 364.39,821.34 363.44,821.34
  pour cut-out: 354.07,878.67 359.55,873.19 361.01,873.19 370.85,883.04 370.85,888.73 364.39,895.2 363.44,895.2
  pour cut-out: 728.1,298.54 733.11,298.54 733.11,287.65 733.05,287.6 728.85,287.6 728.82,287.62
  pour cut-out: 724.33,566.63 731.5,566.63 736.91,561.22 736.91,549.83 729.6,542.53 728.01,542.53
  text "2" at 122.93,99.6 h50
  text ".Layer_Name" at 577,-858.49 h60
POWER_SPLIT_PLANE:
  pour cut-out: 376.83,673 235.05,814.79 235.05,814.88 206.19,814.88 206.19,787.22 348.67,644.74 351.08,644.74
  pour cut-out: 29.46,636.43 25.01,636.43 25.01,645.89 29.77,645.89
  pour cut-out: 29.46,524.56 25.01,524.56 25.01,534.02 29.77,534.02
  pour cut-out: 343.37,672.98 376.83,672.99 376.83,554.5 343.37,554.48
  pour cut-out: 491.14,410.29 491.14,401.79 489.13,399.78 472.44,399.78 469.69,402.52 469.73,402.56 469.73,408.23
  pour cut-out: 728.1,298.54 733.11,298.54 733.11,287.65 733.05,287.6 728.85,287.6 728.82,287.62
  pour cut-out: 724.33,566.63 731.5,566.63 736.91,561.22 736.91,549.83 729.6,542.53 728.01,542.53
  pour cut-out: 422.97,577.9 429.08,577.9 429.08,573.7 427.9,572.52 424.74,572.52 423.04,574.21
  pour cut-out: 422.97,563.92 429.08,563.92 429.08,568.11 427.9,569.3 424.74,569.3 423.04,567.6
  pour cut-out: 262.61,206.82 241.38,228.05 241.38,249.84 252.87,261.33 275.3,261.33 276.56,260.06 276.56,245.83 262.61,231.88
  text "3" at 122.93,99.6 h50
  text ".Layer_Name" at 577,-858.49 h60
Bottom Layer:
  pour cut-out: 728.1,238.54 733.11,238.54 733.11,227.65 733.05,227.6 728.85,227.6 728.82,227.62
  pour cut-out: 724.33,506.63 731.5,506.63 736.91,501.22 736.91,489.83 729.6,482.53 728.01,482.53
  pour cut-out: 551.32,360.81 551.32,352.88 611.64,292.56 611.64,284.07 633.41,262.31 651.1,262.31 703.87,315.08 703.87,332.59 599.08,332.59 559.59,372.08 548.73,372.08 548.73,363.4
  pour cut-out: 354.07,878.67 355.98,878.67 359.83,874.82 370.22,885.22 370.22,888.22 366.22,892.22 365.18,892.22
  text "4" at 156.25,99.28 h50
  text ".Layer_Name" at 577,-858.49 h60

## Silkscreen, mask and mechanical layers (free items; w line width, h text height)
Top Overlay:
  rectangle: 525.41,415.32 532.87,435.78
  lines w6.1: 299.41,550.95 299.41,650.92 304.27,655.78 ; 405.36,344.12 405.36,430.73 ; 416.17,330.69 513.61,330.69 ; 416.17,438.92 514.59,438.92 ; 525.41,342.48 525.41,428.11 ; 622.9,188.04 622.9,128.08 626.42,124.56 ; 672.03,567.23 680.1,575.3 680.1,632.05 694.77,646.72 749.65,646.72 764.31,661.37
  lines w6.5: 222.19,358.02 222.19,50.19 382.83,50.19 678.24,50.19 678.24,557.4 565.31,557.4 547.52,575.2 379.33,575.2 370.38,566.24 370.38,559.35 363.28,552.25 ; 295.85,380.76 295.85,479.8
  text ".Layer_Name" at 577,-858.49 h60
Bottom Overlay:
  text "SYSTEM" at 980.16,909.39 h30
  text "PULL-UP" at 587.72,904.94 h30
  text "BAT" at 451.1,785.8 h30
  text "SYS" at 629.69,784.37 h30
  text "GND" at 114.48,776.38 h30
  text "BAT" at 259.27,776.38 h30
  text "GND" at 809.63,775.07 h30
  text "GND" at 555.71,615.84 h30
  text "CE" at 652.59,615.98 h30
  text "VBUS" at 299.81,585.75 h30
  text "CE" at 724.17,552.94 h30
  text "SDA" at 724.17,452.94 h30
  text "GND" at 269.82,435.95 h30
  text "SCL" at 724.17,352.94 h30
  text "GND" at 502.53,271.36 h30
  text "GND" at 724.17,252.94 h30
  text "SW" at 448.85,217.26 h30
  text "PR2276 Rev-E1" at 785.58,147.13 h30
  text "OTG" at 822.89,22.3 h30
  text "GND" at 926.79,22.29 h30
  text ".Layer_Name" at 577,-858.49 h60
Top Paste:
  text ".Layer_Name" at 577,-858.49 h60
Bottom Paste:
  text ".Layer_Name" at 577,-858.49 h60
Top Solder:
  text ".Layer_Name" at 577,-858.49 h60
  text ".Layer_Name" at 577,-858.49 h60
Bottom Solder:
  text ".Layer_Name" at 577,-858.49 h60
Drill Guide:
  text ".Layer_Name" at 577,-858.49 h60
M1 Board Outline:
  the board outline again, w10
M2 Board Dimensions:
  rectangle: 0,-275 125,-150
  rectangle: 125,-400 500,-275
  lines w7: 0,-275 1000,-275 ; 125,-400 125,-150 ; 250,-400 250,-150 ; 500,-400 500,-150 ; 750,-400 750,-150 ; 0,-400 1000,-400 1000,-150 0,-150 0,-400
M3 3D STEP Top:
  text ".Layer_Name" at 577,-858.49 h60
M4 3D STEP Bottom:
  text ".Layer_Name" at 577,-858.49 h60
M5 Assembly Top:
  circle w6: c905.18,270.17 r10.72
  rectangle: 495.05,678.42 523.11,720.83
  region: 913.12,117.52 885.06,117.52 885.06,75.11 913.12,75.11
  lines w10: -292,-930.17 6308,-930.17 ; -292,-726.83 6310,-726.83 ; -292,-523.5 -292,-1133.5 3713,-1133.5 6310,-1133.5 6310,-523.5 -291.5,-523.5 -291.5,-1133.5 1284,-1133.5 ; 2173,-1133.5 2173,-523.5 ; 3440,-726.83 3440,-523.5 ; 4280,-726.83 4280,-523.5 ; 4902,-1140 4902,-937.17
  text "COMPONENTS MARKED 'DNP' SHOULD NOT BE POPULATED." at 1153.5,-318.5 h60
  text "ASSEMBLY VARIANT:" at 1153,-434 h60
  text ".VariantName" at 2189,-434 h60
  text "PCB VIEWED FROM TOP SIDE" at -228.5,-655.67 h60
  text "BOARD #:" at 2248,-655.67 h60
  text ".PRJ_Number" at 2793.5,-655.67 h60
  text "REV:" at 3638,-655.67 h60
  text ".PCB_Rev" at 3929.5,-655.67 h60
  text "SVN REV:" at 4476,-655.67 h60
  text ".VersionControl_RevNumber" at 4982,-655.67 h60
  text "TOP ASSEMBLY DRAWING" at -228.5,-859 h60
  text "TID #:" at 2248,-859 h60
  text ".TID" at 2793.5,-859 h60
  text "PLOT NAME =" at -228.5,-1064.34 h60
  text ".plot_File_Name" at 577,-1064.34 h60
  text "GENERATED    :" at 2250,-1064.34 h60
  text ".Print_Date" at 3119.5,-1064.34 h60
  text ".Print_Time" at 3848.5,-1064.34 h60
  text "TEXAS INSTRUMENTS" at 5113,-1064.34 h60
M6 Assembly Bottom:
  lines w10: -292.5,-727.33 6309.5,-727.33 ; -290.5,-930.67 6309.5,-930.67 ; 1115.5,-1140.5 1115.5,-937.67 ; 1737.5,-727.33 1737.5,-524 ; 2577.5,-727.33 2577.5,-524 ; 3844.5,-1134 3844.5,-524 ; 4733.5,-1134 6309,-1134 6309,-524 -292.5,-524 -292.5,-1134 2304.5,-1134 6309.5,-1134 6309.5,-524
  text "COMPONENTS MARKED 'DNP' SHOULD NOT BE POPULATED." at 6102,-318 h60
  text ".VariantName" at 5058,-434 h60
  text "ASSEMBLY VARIANT:" at 6097,-434 h60
  text ".VersionControl_RevNumber" at 1035.5,-656.17 h60
  text "SVN REV:" at 1541.5,-656.17 h60
  text ".PCB_Rev" at 2088,-656.17 h60
  text "REV:" at 2379.5,-656.17 h60
  text ".PRJ_Number" at 3224,-656.17 h60
  text "BOARD #:" at 3769.5,-656.17 h60
  text "PCB VIEWED FROM BOTTOM SIDE" at 6246,-656.17 h60
  text ".TID" at 3224,-859.5 h60
  text "TID #:" at 3769.5,-859.5 h60
  text "BOTTOM ASSEMBLY DRAWING" at 6246,-859.5 h60
  text "TEXAS INSTRUMENTS" at 904.5,-1064.84 h60
  text ".Print_Time" at 2169,-1064.84 h60
  text ".Print_Date" at 2898,-1064.84 h60
  text "GENERATED    :" at 3767.5,-1064.84 h60
  text ".plot_File_Name" at 5440.5,-1064.84 h60
  text "PLOT NAME =" at 6246,-1064.84 h60
M9 Title Sheet:
  drawing of 57 lines, arcs and shapes, not listed
  text "1" at 739.84,8036.5 h70
  text "2" at 3235.5,8036.5 h70
  text "3" at 5724.84,8036.5 h70
  text "4" at 8231.51,8036.5 h70
  text "5" at 10730.5,8036.5 h70
  text "6" at 13235.5,8036.5 h70
  text "A" at -416.5,6893.5 h70
  text "A" at 14383.5,6893.5 h70
  text "B" at -416.5,4513.5 h70
  text "B" at 14383.5,4513.5 h70
  text "C" at -416.5,2138.5 h70
  text "C" at 14383.5,2138.5 h70
  text "PROJECT TITLE:" at 11343.5,277.5 h45
  text ".PRJ_Title" at 11393.5,144.17 h70
  text "DESIGNED FOR:" at 11343.5,-23.5 h45
  text ".PRJ_Customer" at 11393.5,-163.5 h70
  text "D" at -416.5,-231.5 h70
  text "D" at 14383.5,-231.5 h70
  text "FILE NAME:" at 11343.5,-323.5 h45
  text ".PCB_File_Name_No_Path" at 11393.5,-443.5 h70
  text "Texas Instruments (TI) and/or its licensors do not warrant the accuracy or completeness of this specification" at 6374,-605.34 h45
  text "ENGINEER:" at 11343.5,-613.5 h45
  text "LAYOUT BY:" at 12848.5,-613.5 h45
  text "or any information contained therein. TI and/or its licensors do not warrant that this design will meet" at 6329.01,-718 h45
  text ".PRJ_Engineer" at 11393.5,-768.49 h70
  text "TESSOLVE" at 12899,-768.49 h70
  text "the specifications, will be suitable for your application or fit for any particular purpose, or will operate in" at 6329.01,-830.67 h45
  text "ALTIUM DESIGNER VERSION:" at 12848.5,-923.5 h45
  text "an implementation. TI and/or its licensors do not warrant that the design is production worthy. You should" at 6329.01,-943.33 h45
  text "completely validate and test your design implementation to confirm the system functionality for your application." at 6374,-1056 h45
  text ".print_Scale" at 11393.5,-1056.83 h70
  text ".Application_BuildNumber" at 12899,-1056.83 h70
  text "1" at 739.84,-1263.5 h70
  text "2" at 3235.5,-1263.5 h70
  text "3" at 5724.84,-1263.5 h70
  text "4" at 8231.51,-1263.5 h70
  text "5" at 10730.5,-1263.5 h70
  text "WO# : 306552-6548-D" at 13235.5,-1263.5 h70
M10 Fab Notes:
  drawing of 193 lines, arcs and shapes, not listed
  text "DESIGN INFORMATION" at 12381.02,5910 h60
  text "MIN. TRACK WIDTH:" at 11736.46,5730 h60
  text "8" at 12832.7,5730 h60
  text "MIL" at 12987.46,5730 h60
  text "MIN. CLEARANCE:" at 11736.46,5598 h60
  text "5.7" at 12772.7,5598 h60
  text "MIL" at 12987.46,5598 h60
  text "MIN. VIA PAD SIZE:" at 11736.46,5466 h60
  text "10" at 12802.71,5466 h60
  text "MIL" at 12987.46,5466 h60
  text "0.05mm (2MIL)" at 12431.46,5324.29 h60
  text "MINIMUM ANNULAR RING" at 11407.23,5320 h60
  text "EXTERNAL" at 13139.46,5320 h60
  text "PER" at 11607.23,5202 h60
  text "IPC-D-275 CLASS 2 LEVEL C" at 11827.23,5202 h60
  text "MIL, HOLES" at 13315.46,5089.71 h60
  text "+/-" at 12923,5089 h60
  text "+/-" at 13777,5089 h60
  text "REGISTRATION TOLERANCES:" at 11407.23,5084 h60
  text "METAL" at 12607,5084 h60
  text "5" at 13183.2,5084 h60
  text "3" at 14016.2,5084 h60
  text "MIL" at 14132.46,5084 h60
  text "MATERIAL:" at 11332.46,4874.54 h60
  text "FR-4 High Tg" at 12318.9,4734.21 h60
  text "FR-408" at 11753.46,4725.64 h60
  text "OTHER" at 13241.46,4725.64 h60
  text "REFER NOTE 1" at 13613.77,4725.64 h60
  text "X" at 13053.79,4725.47 h60
  text "62 MIL (1.6mm) +/-10%" at 12073.56,4562.92 h60
  text "THICKNESS:" at 11407.23,4558.64 h60
  text "OTHER" at 13358.46,4558.64 h60
  text "31MIL +/-10%" at 13653.56,4557.92 h60
  text "X" at 13230,4555 h60
  text "TOLERANCE:" at 11407.23,4400.64 h60
  text "X" at 12246.53,4400.64 h60
  text "ANSI IPC-6012 TYPE 3 CLASS 2" at 12433.48,4400.64 h60
  text "OTHER +/-" at 12433.46,4244.64 h60
  text "BOW & TWIST:" at 11407.23,4087.64 h60
  text "X" at 12246.53,4087.64 h60
  text "ANSI IPC-6012 TYPE 3 CLASS 2" at 12433.48,4087.64 h60
  text "OTHER +/-" at 12433.46,3929.13 h60
  text "DRILLING:" at 11332.46,3790.64 h60
  text "REFERENCE:" at 11407.23,3673.64 h60
  text "X" at 12055.46,3673.64 h60
  text "AS SHOWN" at 12242.46,3673.64 h60
  text "X" at 12956.46,3673.64 h60
  text "NC_DRILL FILES" at 13093.46,3673.64 h60
  text "PTH MIN COPPER THICKNESS:" at 11407.23,3515.64 h60
  text "X" at 12757.46,3515.64 h60
  text "1MIL" at 12894.46,3515.64 h60
  text "OTHER" at 13391.46,3515.64 h60
  text "BOARD FINISH:" at 11332.46,3356.64 h60
  text "SILKSCREEN:" at 11487.68,3238.64 h60
  text "X" at 12436.46,3238.64 h60
  text "TOP" at 12562.46,3238.64 h60
  text "X" at 12946.46,3238.64 h60
  text "BOTTOM" at 13073.46,3238.64 h60
  text "SILKSCREEN COLOR:" at 11487.68,3071.64 h60
  text "X" at 12435.42,3071.64 h60
  text "WHITE" at 12562.46,3071.64 h60
  text "OTHER" at 13073.46,3071.64 h60
  text "FAB NOTES:" at -38.28,3056.77 h100
  text "SOLDER RESIST COLOR:" at 11487.68,2901.64 h60
  text "1. MATERIAL: HIGH-TEMP FR-4, GROUP-3, PER TI SPECIFICATION 6519634 (LATEST REV)." at -29.37,2821.13 h100
  text "X" at 12055.42,2742.44 h60
  text "GREEN" at 12182.46,2742.44 h60
  text "BLUE" at 12773.46,2742.44 h60
  text "OTHER" at 13311.46,2742.44 h60
  text "2. SOLDERMASK CLEARANCE IS GIVEN AS SAME AS PAD SIZE FOR ALL SMT COMPONENTS EXCEPT U1." at -29.37,2596.13 h100
  text "IMMERSION GOLD (ENIG)" at 12393.46,2553.92 h60
  text "ENEPIG" at 13731,2550.64 h60
  text "SURFACE FINISH:" at 11332.46,2549.64 h60
  text "X" at 12206.51,2549.64 h60
  text "VENDOR SHALL OVERSIZE THE MASK CLEARANCES AS PER THEIR MANUFACTURE CAPABILITIES." at 237.82,2408.98 h100
  text "IMM. TIN/SILVER OR EQUIV" at 11662,2392.64 h60
  text "OTHER" at 13093.46,2392.64 h60
  text "ARRAY/PANEL:" at 11332.46,2213.64 h60
  text "CUT AND TRIM PER MECH LAYER 1" at 12393.46,2209.35 h60
  text "3. ALL 6 MIL VIAS NEED TO BE FILLED WITH NON-CONDUCTIVE EPOXY-RESIN AND OVERPLATE WITH COPPER." at -29.37,2160.32 h100
  text "N.C. ROUTE" at 12393.46,2057.64 h60
  text "X" at 13072.46,2057.64 h60
  text "V. SCORE" at 13259.46,2057.64 h60
  text "SURFACE MUST BE FLAT. FLATNESS TOLERANCE IS +0/-1 MIL ON THE TOP SIDE FOR 6 MIL VIAS." at 237.82,1966.9 h100
  text "CERTIFICATION:" at 11332.46,1920.64 h60
  text "MATERIALS AND WORKMANSHIP FOR ALL PCBS" at 12057.46,1920.64 h60
  text "TO MEET OR EXCEED THE REQUIREMENTS OF:" at 12057.46,1822.64 h60
  text "4. POSITIONAL TOLERANCE FOR 6 MIL DRILL SHOULD BE +/-1.5 MIL." at -34.79,1696.85 h100
  text "X" at 11683.96,1686.13 h60
  text "ANSI IPC-A-600F CLASS ->" at 11822.96,1686.13 h60
  text "X" at 13462.02,1686.13 h60
  text "2" at 13580.96,1686.14 h60
  text "1" at 13265.96,1684.64 h60
  text "3" at 13934.96,1684.64 h60
  text "X" at 11686.02,1526.64 h60
  text "UL 94V-0" at 11822.96,1526.64 h60
  text "X" at 12498.02,1526.64 h60
  text "RoHS" at 12634.96,1526.64 h60
  text "OTHER" at 13279.36,1526.64 h60
  text "PER ORDER" at 13676.42,1526.64 h60
  text "ADDITIONAL REQUIREMENTS:" at 11332.46,1385.64 h60
  text "MICROSECTION:" at 11407.23,1270.64 h60
  text "YES" at 12312.96,1270.64 h60
  text "REQUIRED" at 13174.46,1114.49 h60
  text "BARE BOARD ELEC. TEST:" at 11407.23,1111.64 h60
  text "NONE" at 12712.96,1111.64 h60
  text "X" at 13047.46,1111.64 h60
  text "PER ORDER" at 13766.46,1111.64 h60
  text "MANUFACTURER'S UL:" at 11407.23,954.64 h60
  text "RAIL" at 12572.96,950.35 h60
  text "METAL" at 13064.77,950.35 h60
  text "X" at 13440,950 h60
  text "SILK" at 13576.46,950.35 h60
M11 Gerber Information:
  lines w10: -292,-930.17 6308,-930.17 ; -292,-726.83 6310,-726.83 ; -292,-523.5 -292,-1133.5 3713,-1133.5 6310,-1133.5 6310,-523.5 -291.5,-523.5 -291.5,-1133.5 1284,-1133.5 ; 2173,-1133.5 2173,-523.5 ; 3440,-726.83 3440,-523.5 ; 4280,-726.83 4280,-523.5 ; 4902,-1140 4902,-937.17
  text "ALL ARTWORK VIEWED FROM TOP SIDE" at -228.5,-655.67 h60
  text "BOARD #:" at 2248,-655.67 h60
  text ".PRJ_Number" at 2793.5,-655.67 h60
  text "REV:" at 3638,-655.67 h60
  text ".PCB_Rev" at 3929.5,-655.67 h60
  text "SVN REV:" at 4476,-655.67 h60
  text ".VersionControl_RevNumber" at 4982,-655.67 h60
  text "LAYER NAME =" at -228.5,-858.49 h60
  text "TID #:" at 2248,-859 h60
  text ".TID" at 2793.5,-859 h60
  text "GENERATED    :" at 2250,-1064.34 h60
  text ".Print_Date" at 3119.5,-1064.34 h60
  text ".Print_Time" at 3848.5,-1064.34 h60
  text "TEXAS INSTRUMENTS" at 5113,-1064.34 h60
M12 Stackup:
  drawing of 296 lines, arcs and shapes, not listed
  text "LAYER STACKUP:" at 4945.93,5087.27 h100
  text "Layer" at 4998.79,4911.66 h60
  text "Name" at 5408.7,4911.66 h60
  text "Material" at 6538.38,4911.66 h60
  text "Thickness" at 7398.15,4911.66 h60
  text "Constant" at 8047.98,4911.66 h60
  text "Board Layer Stack" at 8617.84,4911.66 h60
  text "1" at 4998.79,4791.66 h60
  text "Top Overlay" at 5408.7,4791.66 h60
  text "2" at 4998.79,4671.66 h60
  text "Top Solder" at 5408.7,4671.66 h60
  text "Solder Resist" at 6538.38,4671.66 h60
  text "3.5" at 8047.98,4671.66 h60
  text "3" at 4998.79,4551.66 h60
  text "Top Layer" at 5408.7,4551.66 h60
  text "Copper" at 6538.38,4551.66 h60
  text "0.5oz+PLATING" at 7355.66,4551.93 h50
  text "4" at 4998.79,4431.66 h60
  text "Dielectric1" at 5408.7,4431.66 h60
  text "FR-4 High TG" at 6538.38,4431.66 h60
  text "TBD" at 7572.98,4431.71 h60
  text "4.2" at 8047.98,4431.66 h60
  text "5" at 4998.79,4311.66 h60
  text "GND" at 5408.7,4311.66 h60
  text "Copper" at 6538.38,4311.66 h60
  text "1OZ" at 7572.98,4311.71 h60
  text "6" at 4998.79,4191.66 h60
  text "Dielectric2" at 5408.7,4191.66 h60
  text "FR-4 High TG" at 6538.38,4191.66 h60
  text "TBD" at 7572.98,4191.71 h60
  text "4.2" at 8047.98,4191.66 h60
  text "7" at 4998.79,4071.66 h60
  text "POWER_SPLIT_PLANE" at 5408.7,4071.66 h60
  text "Copper" at 6538.38,4071.66 h60
  text "1OZ" at 7572.98,4071.71 h60
  text "8" at 4998.79,3951.66 h60
  text "Dielectric3" at 5408.7,3951.66 h60
  text "FR-4 High TG" at 6538.38,3951.66 h60
  text "TBD" at 7572.98,3951.71 h60
  text "4.2" at 8047.98,3951.66 h60
  text "9" at 4998.79,3831.66 h60
  text "Bottom Layer" at 5408.7,3831.66 h60
  text "Copper" at 6538.38,3831.66 h60
  text "0.5oz+PLATING" at 7354.28,3830.04 h50
  text "10" at 4998.79,3711.66 h60
  text "Bottom Solder" at 5408.7,3711.66 h60
  text "Solder Resist" at 6538.38,3711.66 h60
  text "3.5" at 8047.98,3711.66 h60
  text "11" at 4998.79,3591.66 h60
  text "Bottom Overlay" at 5408.7,3591.66 h60
  text "THIS IS A NON-IMPEDANCE CONTROLED BOARD." at 4951.81,3411.22 h100
M13 Component Bodies Top:
  text ".Layer_Name" at 577,-858.49 h60
M14 Component Bodies Bottom:
  text ".Layer_Name" at 577,-858.49 h60
M15 Courtyards Top:
  text ".Layer_Name" at 577,-858.49 h60
M16 Courtyards Bottom:
  text ".Layer_Name" at 577,-858.49 h60
Drill Drawing:
  lines w15: 3902.88,108.88 9201.46,108.88 ; 3902.88,1008.88 9201.46,1008.88 ; 3909.41,1215.08 5055.06,1215.08 ; 4453.75,-41.12 4453.75,1158.88 ; 5043.6,-41.12 5043.6,1158.88 ; 6133.28,-41.12 6133.28,1158.88 ; 6639.16,-41.12 6639.16,1158.88 ; 7372.96,-41.12 7372.96,1158.88 ; 8406.66,-41.12 8406.66,1158.88 ; 3902.88,-41.12 9201.46,-41.12 9201.46,1158.88 3902.88,1158.88 3902.88,-41.12
  text "DRILL CHART:" at 3910.74,1250.84 h100
  text "Symbol" at 3992.88,1053.88 h72
  text "Count" at 4498.75,1053.88 h72
  text "Hole Size" at 5088.6,1053.88 h72
  text "Plated" at 6178.28,1053.88 h72
  text "Hole Type" at 6684.16,1053.88 h72
  text "Tolerance(mil)" at 7417.96,1053.88 h72
  text "Tenting" at 8451.66,1053.88 h72
  text "30" at 4498.75,903.88 h60
  text "6.00mil (0.152mm)" at 5088.6,903.88 h60
  text "PTH" at 6178.28,903.88 h60
  text "Round" at 6684.16,903.88 h60
  text "+0/-6" at 7417.96,903.88 h60
  text "BOTTOM ONLY" at 8451.66,903.88 h60
  text "A" at 3963.79,893.89 h66.67
  text "91" at 4498.75,753.88 h60
  text "12.00mil (0.305mm)" at 5088.6,753.88 h60
  text "PTH" at 6178.28,753.88 h60
  text "Round" at 6684.16,753.88 h60
  text "+0/-12" at 7417.96,753.88 h60
  text "BOTH SIDES" at 8451.66,753.88 h60
  text "B" at 3963.79,743.89 h66.67
  text "2" at 4498.75,603.88 h60
  text "16.00mil (0.406mm)" at 5088.6,603.88 h60
  text "PTH" at 6178.28,603.88 h60
  text "Round" at 6684.16,603.88 h60
  text "+6/-0" at 7417.96,603.88 h60
  text "C" at 3963.79,593.89 h66.67
  text "7" at 4498.75,453.88 h60
  text "40.00mil (1.016mm)" at 5088.6,453.88 h60
  text "PTH" at 6178.28,453.88 h60
  text "Round" at 6684.16,453.88 h60
  text "+/-3" at 7417.96,453.88 h60
  text "D" at 3963.79,443.89 h66.67
  text "4" at 4498.75,303.88 h60
  text "40.16mil (1.020mm)" at 5088.6,303.88 h60
  text "PTH" at 6178.28,303.88 h60
  text "Round" at 6684.16,303.88 h60
  text "+/-3" at 7417.96,303.88 h60
  text "E" at 3963.79,293.89 h66.67
  text "6" at 4498.75,153.88 h60
  text "43.31mil (1.100mm)" at 5088.6,153.88 h60
  text "PTH" at 6178.28,153.88 h60
  text "Round" at 6684.16,153.88 h60
  text "+/-3" at 7417.96,153.88 h60
  text "F" at 3963.79,143.89 h66.67
  text "140 Total" at 4498.75,3.88 h60
  text "FAB" at 577,-858.49 h60

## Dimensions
0,-400 to 1000,-400 on M2 Board Dimensions
0,0 to 1000,0 on M2 Board Dimensions
0,0 to 0,1000 on M2 Board Dimensions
